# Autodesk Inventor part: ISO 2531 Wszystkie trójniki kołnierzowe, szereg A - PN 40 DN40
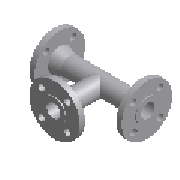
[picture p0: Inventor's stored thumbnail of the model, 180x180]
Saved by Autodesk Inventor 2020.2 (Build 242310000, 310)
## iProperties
Manager: www.cadconsulting.pl
Company: Fabian Stasiak CAD Consulting
Created: 2014-02
Part Number: ISO 2531 Wszystkie trójniki kołnierzowe, szereg A - PN 40 DN40
Material: Żeliwo sferoidalne
Description: Rury, łączniki, akcesoria z żeliwa sferoidalnego i ich złącza do zastosowań w instalacjach wodnych lub gazowych - Wszystkie trójniki kołnierzowe, szereg A - PN
Document SubType Name: Modeling
Standard: ISO 2531
Designer: F.Stasiak
Standard Revision: Fifth edition 1998-08-15
Standards Organization: ISO
Language: pl-PL
Size Designation: DN40
Categories: <MemberInstance><Categories><Category DisplayName="Rury cienko- i grubościenne" InternalName="4347fa0f-2144-441d-94cd-e3e15c92b736" Mnemonic="TUBEANDPIPE"><Cate
Density: 7.15 g/cm^3
Appearance: Ciemnoszary
Catalog Web Link: www.expertbooks.pl
IsCustomPart: 0
NAME: PIPING: ISO 2531 All Flanged Tee Series A - PN 40
DATA: <meta><inlinegroups number="1" deflen="28"></inlinegroups><connections number="3"></connections><angles><a>3.14159265358979</a><a>1.5707963267949</a></angles></
Author: F.Stasiak
Subject: Zbiór ćwiczeń. Autodesk Inventor 2020. Kurs Professional
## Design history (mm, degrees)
sketch "Sketch1"
  geometry: L1 (0, 20)-(280, 20); L2 (280, 20)-(280, 0); L3 (280, 0)-(0, 0); L4 (0, 0)-(0, 20); L5 (0, 20)-(0, 35); L6 (0, 35)-(3, 35); L7 (3, 35)-(3, 75); L8 (3, 75)-(19, 75); L9 (19, 75)-(19, 35); L10 (48.856, 27)-(231.144, 27); L11 (140, 0)-(140, 27); L12 (261, 75)-(261, 35); L13 (277, 75)-(261, 75); L14 (277, 35)-(277, 75); L15 (280, 35)-(277, 35); L16 (280, 20)-(280, 35); L17 (19, 35)-(48.856, 27); L18 (19, 35)-(1.5, 35); L19 (261, 35)-(231.144, 27); L20 (19, 35)-(261, 35); 1 further point
  constraints: 40 end point, 6 parallel, 4 symmetric about line, 3 midpoint, 3 perpendicular, 2 collinear, 2 horizontal, 1 coincident, 5 other
  dimensions: "d0" = 40 diameter of L1 L3 (= ID); "d1" = 7 distance between parallel lines of L1 L10 (= e1); "d2" = 70 diameter of L6 L3 (= N3); "d3" = 150 diameter of L8 L3 (= D); "d4" = 3 distance of L5.end L6.end; "d5" = 19 distance between parallel lines of L9 L5 (= C7); "d6" = 140 distance between parallel lines of L2 L11 (= 0.5 x L); "d22" = 15 deg angle of L10 L17; "d23" = 15 deg angle of L10 L19
revolve "Revolution1" sketch "Sketch1" stored, may be unused: angle "d7" = 90 deg
workplane "Work Plane1"
sketch "Sketch2"
  geometry: L1 (280, 0)-(0, 0) reference; L2 (140, 0)-(140, 27) reference; C1 r 27 at (140, 0); C2 r 20 at (140, 0)
  constraints: 2 centre point, 2 coincident, 1 concentric
  dimensions: "d9" = 40 diameter of C2 (= ID2); "d10" = 54 diameter of C1 (= ID2 + 2 x e2)
extrude "Extrusion1" join sketch "Sketch2" stored distance "d11" = 25.4; taper "d12" = 0 deg
extrude "Extrusion2" cut sketch "Sketch2" stored distance "d13" = 25.4; taper "d14" = 0 deg
sketch "Sketch3"
  geometry: L1 (-120, 121)-(-65, 121); L2 (-65, 121)-(-65, 137); L3 (-65, 137)-(-105, 137); L4 (-105, 137)-(-105, 140); L5 (-105, 140)-(-120, 140); L6 (-120, 140)-(-120, 121); L7 (-120, 121)-(-140, 121); L8 (-140, 121)-(-140, 140); L9 (-140, 140)-(-120, 140); L10 (-160, 140)-(-120, 140) reference; 1 further point
  constraints: 18 end point, 5 parallel, 3 perpendicular, 1 coincident, 1 horizontal
  dimensions: "d15" = 70 diameter of L4 L8 (= N32); "d16" = 3 distance between parallel lines of L3 L5; "d17" = 19 distance between parallel lines of L1 L5 (= C72); "d18" = 150 diameter of L2 L8 (= D2)
revolve "Revolution2" sketch "Sketch3" stored, may be unused: angle "d20" = 90 deg
sketch "Sketch7"
  geometry: L1 (0, 0)-(38.891, 38.891); L2 (0, 0)-(0, 55); C1 r 35 at (0, 0) reference; C2 r 9.5 at (38.891, 38.891); A1 r 55 centre (0, 0) between (38.891, 38.891) and (0, 55)
  constraints: 4 end point, 2 centre point, 2 coincident, 2 point on circle, 1 vertical
  dimensions: "d30" = 19 diameter of C2 (= L2); "d31" = 55 distance of L1.start L1.end (= 0.5 x K1); "d32" = 45 deg angle of L2 L1 (computed from NU)
extrude "Extrusion3" cut sketch "Sketch7" taper "d33" = 0 deg; stored distance "d46" = 10
pattern_circular "Circular Pattern1" dims angle "d36" = 360 deg
sketch "Sketch5"
  geometry: L1 (-215, 121)-(-65, 121) reference; L2 (-167, 121)-(-167, 27) reference; L3 (-113, 121)-(-113, 27) reference; L4 (-167, 121)-(-175, 121); L5 (-175, 121)-(-167, 91.144); L6 (-167, 91.144)-(-167, 121); L7 (-140, 121)-(-140, 27); L8 (-167, 27)-(-113, 27); L9 (-113, 121)-(-105, 121); L10 (-105, 121)-(-113, 91.144); L11 (-113, 91.144)-(-113, 121)
  constraints: 16 end point, 3 perpendicular, 3 symmetric about line, 2 collinear, 2 midpoint, 1 parallel, 3 other
  dimensions: "d24" = 70 diameter of L4.end L7 (= N32); "d25" = 15 deg angle of L2 L5
revolve "Revolution3" sketch "Sketch5" stored, may be unused: angle "d35" = 90 deg
sketch "Sketch6"
  geometry: L1 (0, 0)-(-38.891, 38.891); L2 (0, 0)-(0, 55); C1 r 35 at (0, 0) reference; C2 r 9.5 at (-38.891, 38.891); A1 r 55 centre (0, 0) between (-38.891, 38.891) and (0, 55)
  constraints: 4 end point, 2 centre point, 2 coincident, 2 point on circle, 1 vertical
  dimensions: "d37" = 19 diameter of C2 (= L22); "d39" = 55 distance of L1.start L1.end (= 0.5 x K12); "d40" = 45 deg angle of L2 L1 (computed from NU2)
extrude "Extrusion4" cut sketch "Sketch6" taper "d26" = 0 deg; stored distance "d38" = 10
pattern_circular "Circular Pattern3" dims angle "d28" = 360 deg
sketch "Sketch8"
  geometry: L1 (0, 0)-(0, 55); L2 (0, 0)-(38.891, 38.891); C1 r 35 at (0, 0) reference; C2 r 9.5 at (38.891, 38.891); A1 r 55 centre (0, 0) between (0, 55) and (38.891, 38.891); 1 further point
  constraints: 4 end point, 2 centre point, 2 coincident, 2 point on circle, 1 vertical
  dimensions: "d54" = 110 diameter of A1 (= K1); "d55" = 45 deg angle of L1 L2 (computed from NU); "d56" = 19 diameter of C2 (= L2)
extrude "Extrusion5" cut sketch "Sketch8" stored distance "d57" = 10; taper "d58" = 0 deg
pattern_circular "Circular Pattern5" dims angle "d60" = 360 deg
workaxis "Work Axis2"
workpoint "Work Point1"
workaxis "Work Axis3"
workpoint "Work Point2"
workaxis "Work Axis4"
workpoint "Work Point3"
workaxis "Work Axis5"
workaxis "Work Axis6"
workaxis "Work Axis7"
body "Solid1"
other parameters: "D" = 150 [user parameter; used in 1 equation term], "C7" = 19 [user parameter; used in 1 equation term], "e1" = 7 [user parameter; used in 1 equation term], "ID" = 40 [user parameter; used in 1 equation term], "N3" = 70 [user parameter; used in 1 equation term], "K1" = 110 [user parameter; used in 2 equation terms], "L2" = 19 [user parameter; used in 2 equation terms], "D2" = 150 [user parameter; used in 1 equation term], "C72" = 19 [user parameter; used in 1 equation term], "ID2" = 40 [user parameter; used in 2 equation terms], "N32" = 70 [user parameter; used in 2 equation terms], "e2" = 7 [user parameter; used in 1 equation term], "L22" = 19 [user parameter; used in 1 equation term], "Size_Designation" = 12.345 [user parameter]
